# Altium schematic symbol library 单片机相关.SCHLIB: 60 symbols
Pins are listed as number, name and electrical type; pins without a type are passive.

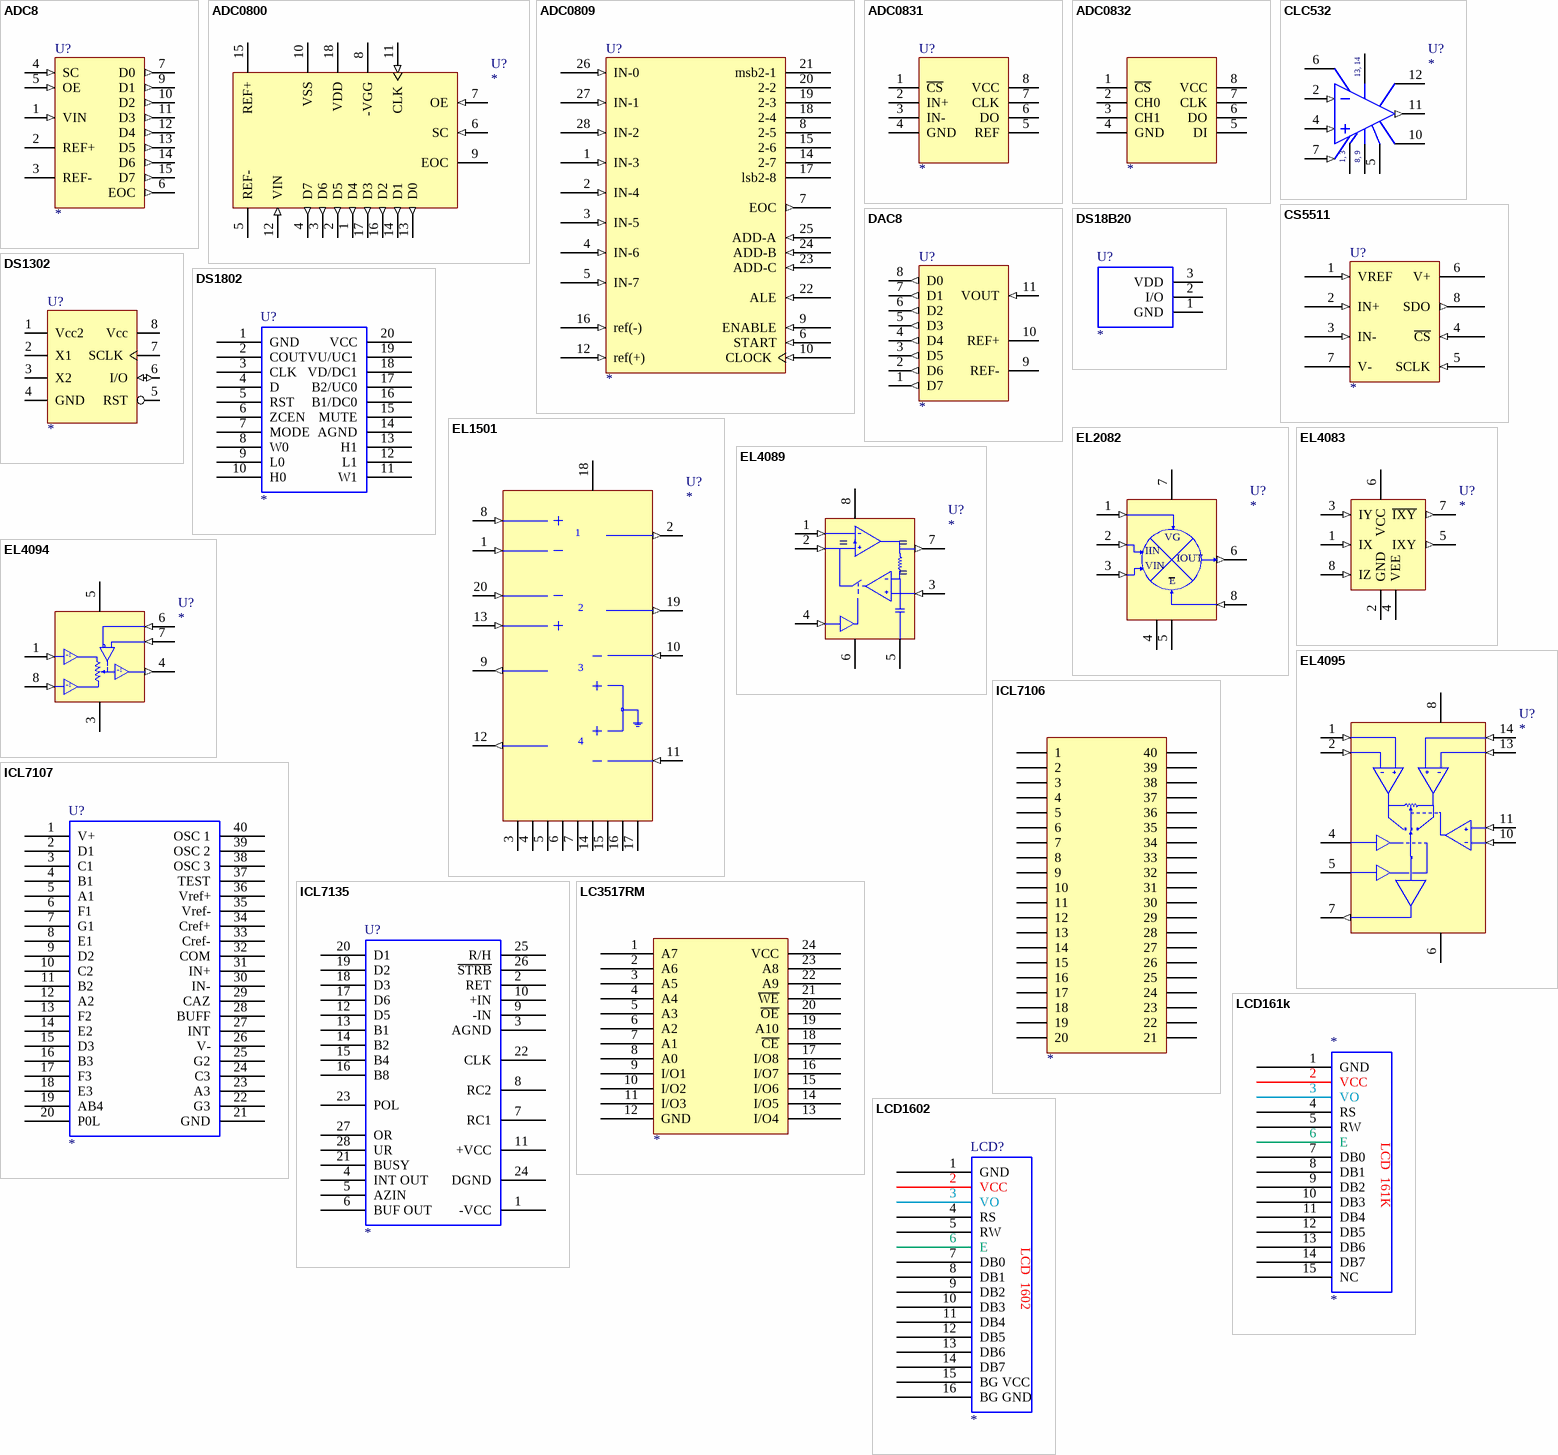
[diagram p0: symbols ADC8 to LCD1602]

## ADC8
designator U?
Generic 8-Bit A/D Converter
simulation model ADC8 (SIMCODE)
pins: 1 VIN (in), 2 REF+, 3 REF-, 4 SC (in), 5 OE (in), 6 EOC (out), 7 D0 (out), 8 GND (power) hidden to GND, 9 D1 (out), 10 D2 (out), 11 D3 (out), 12 D4 (out), 13 D5 (out), 14 D6 (out), 15 D7 (out), 16 VCC (power) hidden to VCC

## ADC0800
designator U?
National 8-Bit Analog to Digital Converter
footprint DIP-18
simulation model ADC0800 (SUBCKT)
pins: 1 D4 (out), 2 D5 (out), 3 D6 (out), 4 D7 (out), 5 REF-, 6 SC (in), 7 OE (in), 8 -VGG (power), 9 EOC, 10 VSS (power), 11 CLK (in), 12 VIN (in), 13 D0 (out), 14 D1 (out), 15 REF+, 16 D2 (out), 17 D3 (out), 18 VDD (power)

## ADC0809
designator U?
footprint DIP28
pins: 1 IN-3 (in), 2 IN-4 (in), 3 IN-5 (in), 4 IN-6 (in), 5 IN-7 (in), 6 START (in), 7 EOC (out), 8 2-5 (hiz), 9 ENABLE (in), 10 CLOCK (in), 12 ref(+) (in), 13 GND (power) hidden to GND, 14 2-7 (hiz), 15 2-6 (hiz), 16 ref(-) (in), 17 lsb2-8 (hiz), 18 2-4 (hiz), 19 2-3 (hiz), 20 2-2 (hiz), 21 msb2-1 (hiz), 22 ALE (in), 23 ADD-C (in), 24 ADD-B (in), 25 ADD-A (in), 26 IN-0 (in), 27 IN-1 (in), 28 IN-2 (in)

## ADC0831
designator U?
ADC
footprint DIP8
pins: 1 ~{CS}, 2 IN+, 3 IN-, 4 GND, 5 REF, 6 DO, 7 CLK, 8 VCC

## ADC0832
designator ?
pins: 1 ~{CS}, 2 CH0, 3 CH1, 4 GND, 5 DI, 6 DO, 7 CLK, 8 VCC

## CLC532
designator U?
High-Speed 2:1 Analog Multiplexer
footprint DIP-14
simulation model CLC532 (SUBCKT)
pins: 1 GND (power), 2 INA- (in), 3 GND (power), 4 INB+ (in), 5 DGND (power), 6 DREF, 7 SEL (in), 8 VEE (power), 9 VEE (power), 10 COMP2, 11 OUT (out), 12 COMP1, 13 VCC (power), 14 VCC (power)

## CS5511
designator U?
National 16-Bit Analog to Digital Converter
pins: 1 VREF (in), 2 IN+ (in), 3 IN- (in), 4 ~{CS} (in), 5 SCLK (in), 6 V+ (power), 7 V- (power), 8 SDO (out)

## DAC8
designator U?
Generic 8-Bit D/A Converter
simulation model DAC8 (SIMCODE)
pins: 1 D7 (out), 2 D6 (out), 3 D5 (out), 4 D4 (out), 5 D3 (out), 6 D2 (out), 7 D1 (out), 8 D0 (out), 9 REF-, 10 REF+, 11 VOUT (in), 12 GND (power) hidden to GND, 13 VCC (power) hidden to VCC

## DS18B20
designator U?
footprint TO-92A
pins: 1 GND, 2 I/O, 3 VDD

## DS1302
designator U?
footprint DIP8
pins: 1 Vcc2, 2 X1, 3 X2, 4 GND, 5 RST, 6 I/O (io), 7 SCLK, 8 Vcc

## DS1802
designator U?
footprint DIP-20
pins: 1 GND, 2 COUT, 3 CLK, 4 D, 5 RST, 6 ZCEN, 7 MODE, 8 W0, 9 L0, 10 H0, 11 W1, 12 L1, 13 H1, 14 AGND, 15 MUTE, 16 B1/DC0, 17 B2/UC0, 18 VD/DC1, 19 VU/UC1, 20 VCC

## EL1501
designator U?
Differential line Driver/Receiver
footprint DIP-20
simulation model EL1501 (SUBCKT)
pins: 1 DRV+ IN- (in), 2 DRV+ OUT (out), 3 VEE (power), 4 GND (power), 5 GND (power), 6 GND (power), 7 GND (power), 8 DRV+ IN+ (in), 9 RX+ OUT1 (out), 10 RX+ IN1- (in), 11 RX- IN2- (in), 12 RX- OUT2 (out), 13 DRV- IN+ (in), 14 GND (power), 15 GND (power), 16 GND (power), 17 GND (power), 18 VCC (power), 19 DRV- OUT (out), 20 DRV- IN- (in)

## EL2082
designator U?
Current-Mode Multiplier
footprint DIP-8
simulation model EL2082 (SUBCKT)
pins: 1 VG (in), 2 IIN (in), 3 VIN (in), 4 VEE (power), 5 GND (power), 6 IOUT (out), 7 VCC (power), 8 ~{E} (in)

## EL4083
designator U?
Current Mode Four Quadrant Multiplier
footprint DIP-8
simulation model EL4083 (SUBCKT)
pins: 1 IX (in), 2 GND (power), 3 IY (in), 4 VEE (power), 5 IXY (out), 6 VCC (power), 7 ~{IXY} (out), 8 IZ (in)

## EL4089
designator U?
DC Restored Video Amplifier
footprint DIP-8
simulation model EL4089 (SUBCKT)
pins: 1 IN- (in), 2 IN+ (in), 3 S/H (in), 4 HOLD (in), 5 GND (power), 6 V- (power), 7 OUT (out), 8 V+ (power)

## EL4094
designator U?
Video Gain Control/Fader
footprint DIP-8
simulation model EL4094 (SUBCKT)
pins: 1 INB (in), 2 GND (power) hidden to GND, 3 V- (power), 4 OUT (out), 5 V+ (power), 6 ~{VG} (in), 7 VG (in), 8 INA (in)

## EL4095
designator U?
Video Gain Contol/Fader/Multiplexer
footprint DIP-14
simulation model EL4095 (SUBCKT)
pins: 1 +INB (in), 2 -INB (in), 3 GND (power) hidden to GND, 4 ~{FORCE A}, 5 ~{FORCE B}, 6 V- (power), 7 V OUT (out), 8 V+ (power), 10 ~{V G} (in), 11 V G (in), 13 -INA (in), 14 +INA (in)

## ICL7106
designator ?
pins: 1, 2, 3, 4, 5, 6, 7, 8, 9, 10, 11, 12, 13, 14, 15, 16, 17, 18, 19, 20, 21, 22, 23, 24, 25, 26, 27, 28, 29, 30, 31, 32, 33, 34, 35, 36, 37, 38, 39, 40

## ICL7107
designator U?
footprint DIP-40
pins: 1 V+, 2 D1, 3 C1, 4 B1, 5 A1, 6 F1, 7 G1, 8 E1, 9 D2, 10 C2, 11 B2, 12 A2, 13 F2, 14 E2, 15 D3, 16 B3, 17 F3, 18 E3, 19 AB4, 20 P0L, 21 GND, 22 G3, 23 A3, 24 C3, 25 G2, 26 V-, 27 INT, 28 BUFF, 29 CAZ, 30 IN-, 31 IN+, 32 COM, 33 Cref-, 34 Cref+, 35 Vref-, 36 Vref+, 37 TEST, 38 OSC 3, 39 OSC 2, 40 OSC 1

## ICL7135
designator U?
footprint DIP-28
pins: 1 -VCC, 2 RET, 3 AGND, 4 INT OUT, 5 AZIN, 6 BUF OUT, 7 RC1, 8 RC2, 9 -IN, 10 +IN, 11 +VCC, 12 D5, 13 B1, 14 B2, 15 B4, 16 B8, 17 D6, 18 D3, 19 D2, 20 D1, 21 BUSY, 22 CLK, 23 POL, 24 DGND, 25 R/H, 26 ~{STRB}, 27 OR, 28 UR

## LC3517RM
designator ?
pins: 1 A7, 2 A6, 3 A5, 4 A4, 5 A3, 6 A2, 7 A1, 8 A0, 9 I/O1, 10 I/O2, 11 I/O3, 12 GND, 13 I/O4, 14 I/O5, 15 I/O6, 16 I/O7, 17 I/O8, 18 ~{CE}, 19 A10, 20 ~{OE}, 21 ~{WE}, 22 A9, 23 A8, 24 VCC

## LCD161k
designator *
footprint HDR1X15 (Connector; Header; 15 Position)
pins: 1 GND, 2 VCC, 3 VO, 4 RS, 5 RW, 6 E, 7 DB0, 8 DB1, 9 DB2, 10 DB3, 11 DB4, 12 DB5, 13 DB6, 14 DB7, 15 NC

## LCD1602
designator LCD?
footprint 1602LCD (LCD module 16*2 char)
pins: 1 GND, 2 VCC, 3 VO, 4 RS, 5 RW, 6 E, 7 DB0, 8 DB1, 9 DB2, 10 DB3, 11 DB4, 12 DB5, 13 DB6, 14 DB7, 15 BG VCC, 16 BG GND

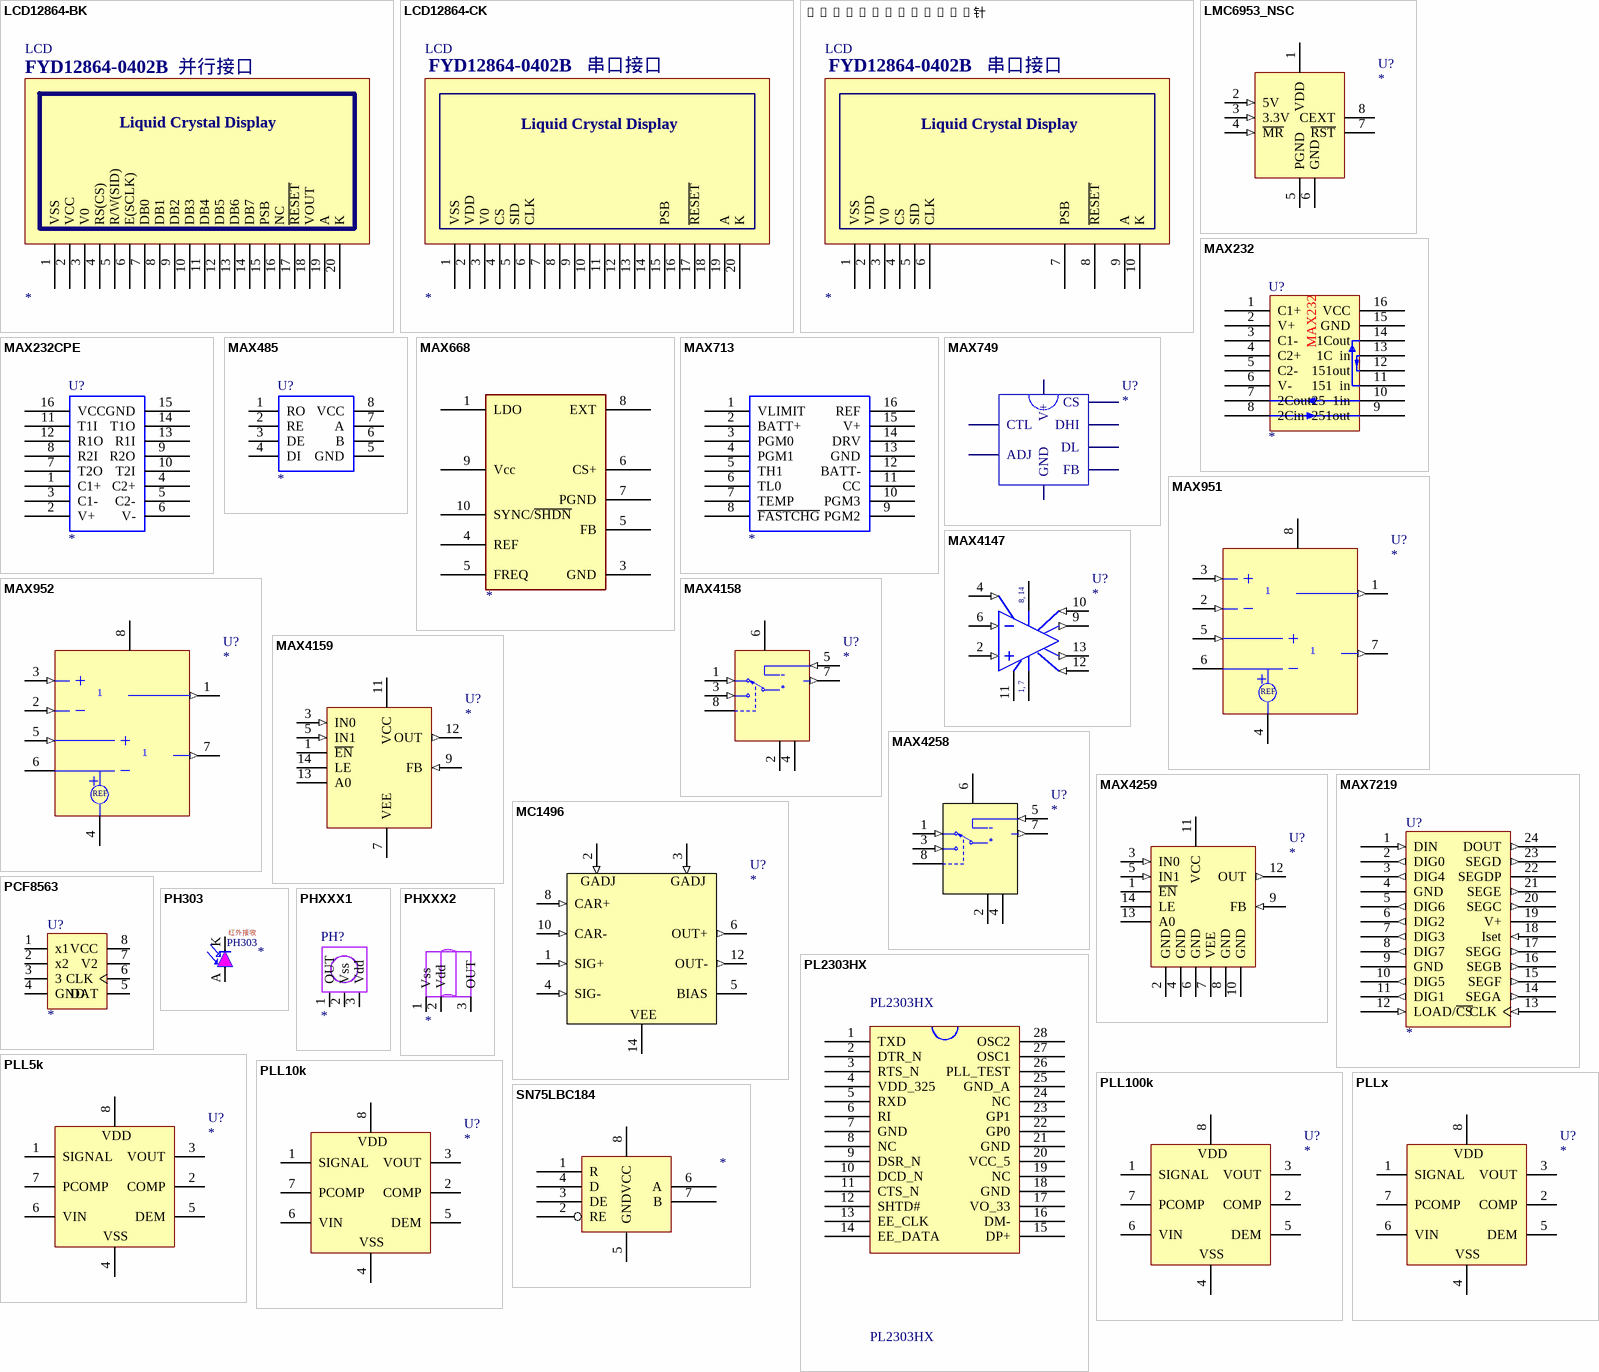
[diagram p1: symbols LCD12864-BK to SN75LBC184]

## LCD12864-BK
designator LCD
footprint SIP20
pins: 1    VSS, 2    VCC, 3    V0, 4    RS(CS), 5    R/W(SID), 6    E(SCLK), 7    DB0, 8    DB1, 9    DB2, 10    DB3, 11    DB4, 12    DB5, 13    DB6, 14    DB7, 15    PSB, 16    NC, 17    ~{RESET}, 18    VOUT, 19    A, 20    K

## LCD12864-CK
designator LCD
footprint SIP20
pins: 1    VSS, 2    VDD, 3    V0, 4    CS, 5    SID, 6    CLK, 7, 8, 9, 10, 11, 12, 13, 14, 15    PSB, 16, 17    ~{RESET}, 18, 19    A, 20    K

## LCD12864-CK10针
designator LCD
footprint SIP10
pins: 1    VSS, 2    VDD, 3    V0, 4    CS, 5    SID, 6    CLK, 7    PSB, 8    ~{RESET}, 9    A, 10    K

## LMC6953_NSC
designator U?
PCI Local Bus Power Supervisor
footprint SO8
simulation model LMC6953_NSC (SUBCKT)
pins: 1 VDD (power), 2 5V (in), 3 3.3V (in), 4 ~{MR} (in), 5 PGND (power), 6 GND (power), 7 ~{RST} (oc), 8 CEXT

## MAX232
designator U?
footprint DIP16
pins: 1 C1+, 2 V+, 3 C1-, 4 C2+, 5 C2-, 6 V-, 7 2Cout, 8 2Cin, 9 251out, 10 25  1in, 11 151  in, 12 151out, 13 1C  in, 14 1Cout, 15 GND, 16 VCC

## MAX232CPE
designator U?
footprint DIP-16
pins: 1 C1+, 2 V+, 3 C1-, 4 C2+, 5 C2-, 6 V-, 7 T2O, 8 R2I, 9 R2O, 10 T2I, 11 T1I, 12 R1O, 13 R1I, 14 T1O, 15 GND, 16 VCC

## MAX485
designator U?
footprint DIP-4
pins: 1 RO, 2 RE, 3 DE, 4 DI, 5 GND, 6 B, 7 A, 8 VCC

## MAX668
designator ?
pins: 1 LDO, 3 GND, 4 REF, 5 FREQ, 5 FB, 6 CS+, 7 PGND, 8 EXT, 9 Vcc, 10 SYNC/~{SHDN}

## MAX713
designator ?
pins: 1 VLIMIT, 2 BATT+, 3 PGM0, 4 PGM1, 5 TH1, 6 TL0, 7 TEMP, 8 ~{FASTCHG}, 9 PGM2, 10 PGM3, 11 CC, 12 BATT-, 13 GND, 14 DRV, 15 V+, 16 REF

## MAX749
designator U?
footprint DIP8
pins: 1 V+, 2 ADJ, 3 CTL, 4 FB, 5 GND, 6 DL, 7 DHI, 8 CS

## MAX951
designator U?
Ultra-Low-Power, Single-Supply Op Amp + Comparator + Reference
simulation model MAX951 (SUBCKT)
pins: 1 AMPOUT (out), 2 AMPIN- (in), 3 AMPIN+ (in), 4 VEE (power), 5 COMPIN+ (in), 6 REF/COMPIN-, 7 COMPOUT (out), 8 VCC (power)

## MAX952
designator U?
Ultra-Low-Power, Single-Supply Op Amp + Comparator + Reference
simulation model MAX952 (SUBCKT)
pins: 1 AMPOUT (out), 2 AMPIN- (in), 3 AMPIN+ (in), 4 VEE (power), 5 COMPIN+ (in), 6 REF/COMPIN-, 7 COMPOUT (out), 8 VCC (power)

## MAX4147
designator U?
300MHz, Low-Power, High-Output-Current, Differential Line Driver; Text Field6: Pins 3 and 5 are not connected
simulation model MAX4147 (SUBCKT)
pins: 1 VEE (power), 2 IN+ (in), 4 SD (in), 6 IN- (in), 7 VEE (power), 8 VCC (power), 9 OUT- (out), 10 SEN- (in), 11 GND (power), 12 SEN+ (in), 13 OUT+ (out), 14 VCC (power)

## MAX4158
designator U?
350MHz 2-Channel Video Multiplexer-Amplifier; Text Field6: Due to manufacturer's model IN0 is always selected independent of A0 (stupid huh?)
simulation model MAX4158 (SUBCKT)
pins: 1 IN0 (in), 2 GND (power), 3 IN1 (in), 4 VEE (power), 5 FB (in), 6 VCC (power), 7 OUT (out), 8 A0

## MAX4159
designator U?
350MHz 2-Channel Video Multiplexer-Amplifier; Text Field6: Due to manufacturer's model IN0 is always selected independent of A0 (stupid huh?)
simulation model MAX4159 (SUBCKT)
pins: 1 ~{EN}, 2 GND (power) hidden to GND, 3 IN0 (in), 4 GND (power) hidden to GND, 5 IN1 (in), 6 GND (power) hidden to GND, 7 VEE (power), 8 GND (power) hidden to GND, 9 FB (in), 10 GND (power) hidden to GND, 11 VCC (power), 12 OUT (out), 13 A0, 14 LE

## MAX4258
designator U?
250MHz, 2-Channel Video Multiplexer-Amplifier; Text Field6: Due to manufacturer's model IN0 is always selected independent of A0 (stupid huh?)
simulation model MAX4258 (SUBCKT)
pins: 1 IN0 (in), 2 GND (power), 3 IN1 (in), 4 VEE (power), 5 FB (in), 6 VCC (power), 7 OUT (out), 8 A0

## MAX4259
designator U?
250MHz 2-Channel Video Multiplexer-Amplifier; Text Field6: Due to manufacturer's model IN0 is always selected independent of A0 (stupid huh?)
simulation model MAX4259 (SUBCKT)
pins: 1 ~{EN}, 2 GND (power), 3 IN0 (in), 4 GND (power), 5 IN1 (in), 6 GND (power), 7 VEE (power), 8 GND (power), 9 FB (in), 10 GND (power), 11 VCC (power), 12 OUT (out), 13 A0, 14 LE

## MAX7219
designator U?
footprint DIP24
pins: 1 DIN (in), 2 DIG0 (out), 3 DIG4 (out), 4 GND (power), 5 DIG6 (out), 6 DIG2 (out), 7 DIG3 (out), 8 DIG7 (out), 9 GND (power), 10 DIG5 (out), 11 DIG1 (out), 12 LOAD/~{CS} (in), 13 CLK (in), 14 SEGA (out), 15 SEGF (out), 16 SEGB (out), 17 SEGG (out), 18 Iset (in), 19 V+ (power), 20 SEGC (out), 21 SEGE (out), 22 SEGDP, 23 SEGD (out), 24 DOUT (out)

## MC1496
designator U?
Balanced Modulator/Demodulator
footprint DIP-14
simulation model MC1496 (SUBCKT)
pins: 1 SIG+ (in), 2 GADJ (in), 3 GADJ (in), 4 SIG- (in), 5 BIAS, 6 OUT+ (out), 8 CAR+ (in), 10 CAR- (in), 12 OUT- (out), 14 VEE (power)

## PCF8563
designator U?
footprint DIP8
pins: 1 x1, 2 x2, 3, 4 GND, 5 DAT, 6 CLK, 7 V2, 8 VCC

## PH303
designator ?
pins: A, K

## PHXXX1
designator PH?
footprint TO-220
pins: 1 OUT, 2 Vss, 3 Vdd

## PHXXX2
designator ?
footprint TO-220
pins: 1 Vss, 2 Vdd, 3 OUT

## PL2303HX
designator PL2303HX
footprint SSOP28 (SSOP, 28-Leads, 10.5x5.6mm (max), 0.65mm)
pins: 1 TXD, 2 DTR_N, 3 RTS_N, 4 VDD_325, 5 RXD, 6 RI, 7 GND, 8 NC, 9 DSR_N, 10 DCD_N, 11 CTS_N, 12 SHTD#, 13 EE_CLK, 14 EE_DATA, 15 DP+, 16 DM-, 17 VO_33, 18 GND, 19 NC, 20 VCC_5, 21 GND, 22 GP0, 23 GP1, 24 NC, 25 GND_A, 26 PLL_TEST, 27 OSC1, 28 OSC2

## PLL5k
designator U?
Generic Phase Locked Loop
simulation model PLL5k (SUBCKT)
pins: 1 SIGNAL, 2 COMP, 3 VOUT, 4 VSS, 5 DEM, 6 VIN, 7 PCOMP, 8 VDD

## PLL10k
designator U?
Generic Phase Locked Loop
simulation model PLL10k (SUBCKT)
pins: 1 SIGNAL, 2 COMP, 3 VOUT, 4 VSS, 5 DEM, 6 VIN, 7 PCOMP, 8 VDD

## PLL100k
designator U?
Generic Phase Locked Loop
simulation model PLL100k (SUBCKT)
pins: 1 SIGNAL, 2 COMP, 3 VOUT, 4 VSS, 5 DEM, 6 VIN, 7 PCOMP, 8 VDD

## PLLx
designator U?
Generic Phase Locked Loop
simulation model PLLx (SUBCKT)
pins: 1 SIGNAL, 2 COMP, 3 VOUT, 4 VSS, 5 DEM, 6 VIN, 7 PCOMP, 8 VDD

## SN75LBC184
designator ?
pins: 1 R, 2 RE, 3 DE, 4 D, 5 GND, 6 A, 7 B, 8 VCC

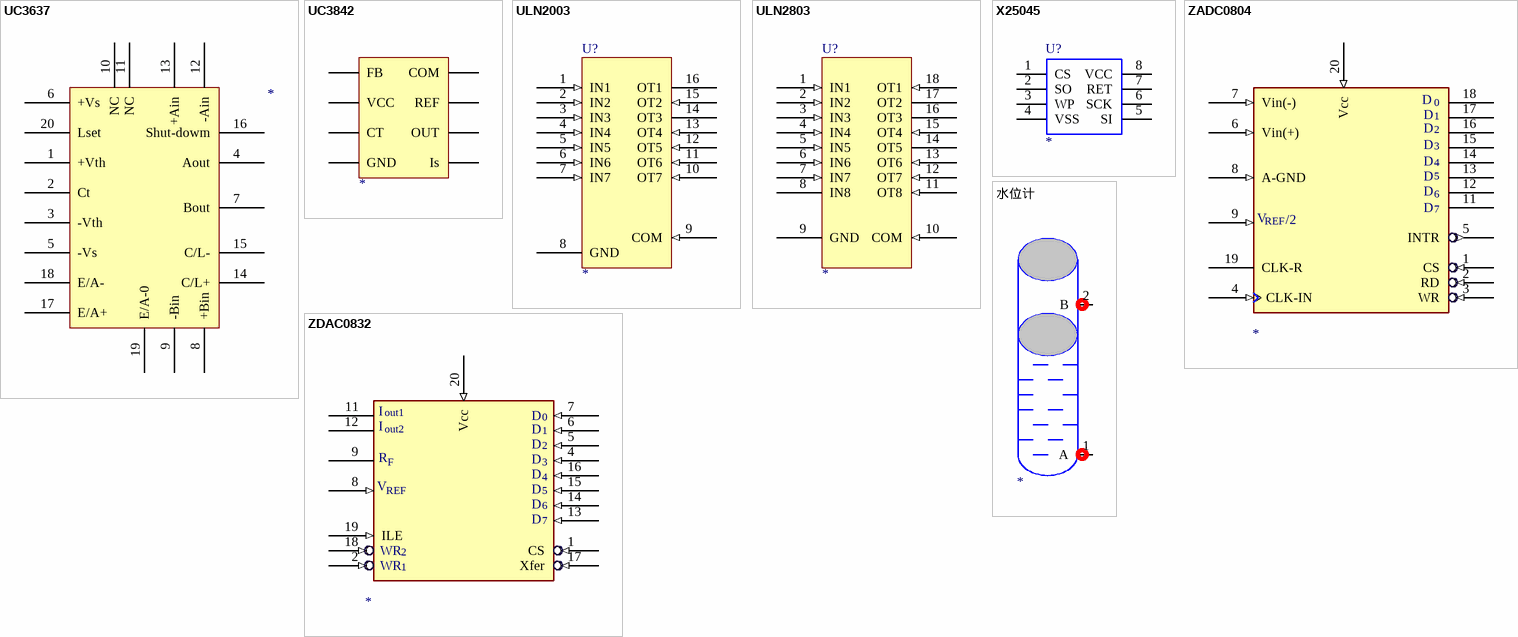
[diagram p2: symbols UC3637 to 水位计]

## UC3637
designator ?
pins: 1 +Vth, 2 Ct, 3 -Vth, 4 Aout, 5 -Vs, 6 +Vs, 7 Bout, 8 +Bin, 9 -Bin, 10 NC, 11 NC, 12 -Ain, 13 +Ain, 14 C/L+, 15 C/L-, 16 Shut-dowm, 17 E/A+, 18 E/A-, 19 E/A-0, 20 Lset

## UC3842
designator ?
pins: 1 COM, 2 FB, 3 Is, 4 CT, 5 GND, 6 OUT, 7 VCC, 8 REF

## ULN2003
designator U?
footprint DIP16
pins: 1 IN1 (in), 2 IN2 (in), 3 IN3 (in), 4 IN4 (in), 5 IN5 (in), 6 IN6 (in), 7 IN7 (in), 8 GND (power), 9 COM (in), 10 OT7 (in), 11 OT6 (in), 12 OT5 (in), 13 OT4 (in), 14 OT3 (hiz), 15 OT2 (in), 16 OT1 (power)

## ULN2803
designator U?
footprint DIP18
pins: 1 IN1 (in), 2 IN2 (in), 3 IN3 (in), 4 IN4 (in), 5 IN5 (in), 6 IN6 (in), 7 IN7 (in), 8 IN8, 9 GND (power), 10 COM (in), 11 OT8 (in), 12 OT7 (in), 13 OT6 (in), 14 OT5 (hiz), 15 OT4 (in), 16 OT3 (power), 17 OT2, 18 OT1 (in)

## X25045
designator U?
footprint DIP-4
pins: 1 CS, 2 SO, 3 WP, 4 VSS, 5 SI, 6 SCK, 7 RET, 8 VCC

## ZADC0804
designator ?
pins: 1 CS (in), 2 RD (in), 3 WR (in), 4 CLK-IN (in), 5 INTR (out), 6 Vin(+) (in), 7 Vin(-) (in), 8 A-GND (in), 9 Vref/2 (in), 10 GND (power) hidden to GND, 11 msbDB7 (hiz), 12 DB6 (hiz), 13 DB5 (hiz), 14 DB4 (hiz), 15 DB3 (hiz), 16 DB2 (hiz), 17 DB1 (hiz), 18 lsbDB0 (hiz), 19 CLK-R, 20 Vcc (in)

## ZDAC0832
designator ?
pins: 1 CS (in), 2 WR1 (in), 3 GND (power) hidden to GND, 4 DI3 (in), 5 DI2 (in), 6 DI1 (in), 7 lsbDI0 (in), 8 Vref (in), 9 Rfb, 10 GND (power) hidden to GND, 11 Iout1, 12 Iout2, 13 msbDI7 (in), 14 DI6 (in), 15 DI5 (in), 16 DI4 (in), 17 Xfer (in), 18 WR2 (in), 19 ILE (in), 20 Vcc (in)

## 水位计
designator ?
pins: 1 A, 2 B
